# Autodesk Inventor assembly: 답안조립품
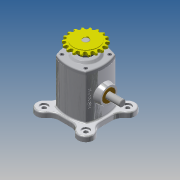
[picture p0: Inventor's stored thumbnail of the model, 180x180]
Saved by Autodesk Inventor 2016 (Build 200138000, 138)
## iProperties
Created: 2016-05
Part Number: 답안조립품
Document SubType Name: Assembly
Designer: Administrator
Author: Administrator
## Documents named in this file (11)
- D:\460508V1003\답안조립품.iam
- D:\460508V1003\본체.ipt
- D:\460508V1003\커버.ipt
- D:\460508V1003\오일실.ipt
- D:\460508V1003\베어링-6203.ipt
- D:\460508V1003\M4x0.7x12.ipt
- D:\460508V1003\편심축.ipt
- D:\460508V1003\키5x5.ipt
- D:\460508V1003\스프로킷.ipt
- D:\460508V1003\슬라이더.ipt
- D:\460508V1003\부시.ipt
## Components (8 placed, 1 different names)
1. M4x0.7x12:1
2. M4x0.7x12:2
3. M4x0.7x12:3
4. M4x0.7x12:4
5. M4x0.7x12:5
6. M4x0.7x12:6
7. M4x0.7x12:7
8. M4x0.7x12:8
